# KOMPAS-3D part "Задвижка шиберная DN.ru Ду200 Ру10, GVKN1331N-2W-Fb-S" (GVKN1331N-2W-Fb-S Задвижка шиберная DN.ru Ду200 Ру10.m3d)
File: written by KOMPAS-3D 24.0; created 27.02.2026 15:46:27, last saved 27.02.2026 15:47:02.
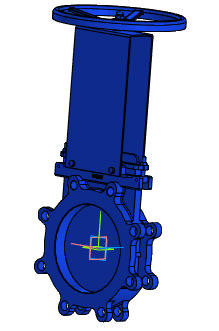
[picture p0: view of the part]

Document properties: Автор: R2D2; Полное имя файла: GVKN1331N-2W-Fb-S Задвижка шиберная DN.ru Ду200 Ру10.cdw

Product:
- Part/product: Задвижка шиберная DN.ru Ду200 Ру10  | designation GVKN1331N-2W-Fb-S
    Масса: 26.5
    Раздел спецификации: Прочие изделия
    Форматы листов документа: A2
    Примечание: D040-07897
    additional columns: D040-07897

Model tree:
1. Операция без истории:1

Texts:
  GVKN1331N-2W-Fb-S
